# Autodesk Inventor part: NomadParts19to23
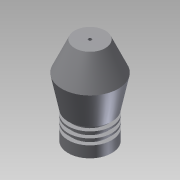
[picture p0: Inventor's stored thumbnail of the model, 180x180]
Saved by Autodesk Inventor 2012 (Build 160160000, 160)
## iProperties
Created: 2012-10
Part Number: NomadParts19to23
Material: Default
Document SubType Name: Modeling
Designer: TechShop Member
Density: 1 g/cm^3
Author: TechShop Member
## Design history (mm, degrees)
sketch "Sketch1"
  geometry: L1 (0, 138.402)-(24.13, 138.402); L2 (27.983, 43.152)-(34.333, 43.152); L3 (0, 0)-(27.983, 0); L4 (27.983, 0)-(34.333, 0); L5 (44.45, 93.017)-(34.333, 43.152); L6 (24.13, 138.402)-(44.45, 93.017); L7 (27.983, 43.152)-(27.983, 36.802); L8 (27.983, 36.802)-(34.333, 36.802); L9 (34.333, 36.802)-(34.333, 33.627); L10 (34.333, 33.627)-(27.983, 33.627); L11 (27.983, 33.627)-(27.983, 27.277); L12 (27.983, 27.277)-(34.333, 27.277); L13 (34.333, 27.277)-(34.333, 24.102); L14 (34.333, 24.102)-(27.983, 24.102); L15 (27.983, 24.102)-(27.983, 17.752); L16 (27.983, 17.752)-(34.333, 17.752); L17 (34.333, 17.752)-(34.333, 0); L18 (0, 138.402)-(0, 0)
  constraints: 36 end point, 7 perpendicular, 6 parallel, 1 collinear
  dimensions: "d8" = 24.13 distance of L1.start L1.end; "d11" = 6.35 distance of L2.start L2.end; "d12" = 27.98293 distance of L3.start L3.end; "d13" = 6.35 distance of L3.end L4.end; "d14" = 6.35 distance of L2.start L7.end; "d15" = 6.35 distance of L7.end L8.end; "d16" = 3.175 distance of L8.end L9.end; "d17" = 6.35 distance of L9.end L10.end
revolve "Revolution1" sketch "Sketch1" stored, may be unused: angle "d18" = 90 deg
sketch "Sketch2"
  geometry: C1 r 24.13 at (0, 0) reference; 1 further point
  constraints: 1 coincident
hole "Hole1" sketch "Sketch2" at (0, 0) diameter "d19" = 5.207; stored, may be unused: countersink angle "d23" = 82 deg, drill point angle "d25" = 118 deg; dims "d20" = 19.05, "d21" = 9.525, "d22" = 6.35, "d24" = 25.4
body "Solid1"
